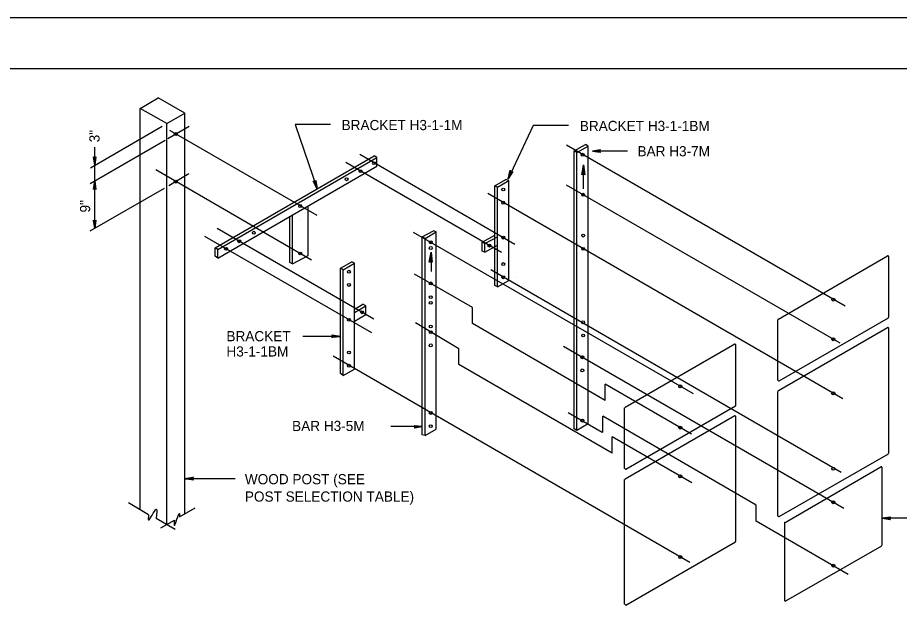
# Model space of a CAD drawing. Extents: x 648590 to 650336, y 294467 to 295061.
# Drawn here: x 649713.9 to 649974.1, y 294884.8 to 295061.4 of the extents above; entities that cross this region are included whole.
import ezdxf

# ---------------------------------------------------------------- set-up
doc = ezdxf.new("R2010")
doc.units = 0
for name, color, linetype in [('1', 7, 'Continuous'), ('2', 7, 'Continuous'), ('3', 7, 'Continuous'), ('PLT-BNDY', 7, 'Continuous')]:
    doc.layers.add(name, color=color, linetype=linetype)

msp = doc.modelspace()

# ---------------------------------------------------------------- linework, layer by layer
at = {"layer": '1'}
msp.add_line((649471.1, 295046.45), (650257.1, 295046.45), dxfattribs=at)
at = {"layer": '2'}
for points in [[(649806.17, 295029.92), (649795.72, 295029.92), (649802.22, 295010.92)], [(649876.38, 295029.67), (649865.97, 295029.67), (649858.6, 295013.92)], [(649885.72, 295021.79), (649885.72, 295021.92), (649883.47, 295022.04), (649885.72, 295021.79), (649885.85, 295021.67), (649883.47, 295022.04), (649885.72, 295022.17), (649885.72, 295022.42), (649883.47, 295022.04), (649885.85, 295022.42), (649885.72, 295022.42)], [(649893.85, 295022.04), (649883.47, 295022.04)], [(649859.85, 295015.92), (649859.6, 295015.92), (649858.6, 295013.92), (649859.85, 295015.92), (649859.97, 295016.04), (649858.6, 295013.92), (649859.47, 295016.04), (649859.35, 295016.17), (649858.6, 295013.92), (649859.22, 295016.42), (649859.35, 295016.17)], [(649801.72, 295013.29), (649801.6, 295013.17), (649802.22, 295010.92), (649801.72, 295013.29), (649801.85, 295013.42), (649802.22, 295010.92), (649801.35, 295013.04), (649801.22, 295013.17), (649802.22, 295010.92), (649801.1, 295013.17), (649801.22, 295013.17)], [(649809.1, 294967.42), (649797.97, 294967.42)], [(649806.72, 294967.79), (649806.85, 294967.54), (649809.1, 294967.42), (649806.72, 294967.79), (649806.6, 294967.92), (649809.1, 294967.42), (649806.85, 294967.29), (649806.85, 294967.17), (649809.1, 294967.42), (649806.6, 294967.04), (649806.85, 294967.17)], [(649833.22, 294940.79), (649824.03, 294940.79)], [(649830.97, 294941.04), (649830.97, 294940.92), (649833.22, 294940.79), (649830.97, 294941.04), (649830.85, 294941.17), (649833.22, 294940.79), (649830.97, 294940.67), (649830.97, 294940.42), (649833.22, 294940.79), (649830.85, 294940.42), (649830.97, 294940.42)], [(649765.6, 294925.17), (649765.47, 294925.29), (649763.22, 294925.42), (649765.6, 294925.17), (649765.72, 294925.04), (649763.22, 294925.42), (649765.47, 294925.54), (649765.6, 294925.79), (649763.22, 294925.42), (649765.72, 294925.92), (649765.6, 294925.79)], [(649778, 294925.42), (649763.22, 294925.42)], [(649971.35, 294913.42), (649971.22, 294913.67), (649968.97, 294913.79), (649971.35, 294913.42), (649971.47, 294913.29), (649968.97, 294913.79), (649971.22, 294913.92), (649971.35, 294914.04), (649968.97, 294913.79), (649971.47, 294914.17), (649971.35, 294914.04)], [(649979.04, 294913.79), (649968.97, 294913.79)]]:
    msp.add_lwpolyline(points, dxfattribs=at)
at = {"layer": '3'}
for p, q in [((649749.97, 295034.67), (649755.35, 295037.79)), ((649763.22, 295033.29), (649755.35, 295037.79)), ((649749.97, 294916.42), (649749.97, 295034.67)), ((649757.85, 295030.17), (649749.97, 295034.67)), ((649757.85, 295030.17), (649763.22, 295033.29)), ((649763.22, 294914.92), (649763.22, 295033.29)), ((649735.35, 295017.17), (649756.47, 295029.42)), ((649757.85, 294911.79), (649757.85, 295030.17)), ((649758.22, 295025.79), (649764.47, 295029.42)), ((649802.22, 295003.04), (649758.72, 295028.17)), ((649760.6, 295027.04), (649760.6, 295027.04)), ((649735.22, 295012.54), (649757.35, 295025.29)), ((649736.6, 295013.34), (649736.6, 295023.19)), ((649958.1, 294976.29), (649875.85, 295023.79)), ((649878.1, 295022.17), (649881.47, 295024.04)), ((649878.85, 295021.67), (649882.22, 295023.54)), ((649882.22, 295023.54), (649881.47, 295024.04)), ((649882.22, 294941.67), (649882.22, 295023.54)), ((649772.1, 294993.54), (649819.1, 295020.67)), ((649860.6, 294994.54), (649814.85, 295021.04)), ((649818.47, 295020.42), (649818.47, 295020.42)), ((649819.85, 295020.17), (649819.1, 295020.67)), ((649878.1, 294940.17), (649878.1, 295022.17)), ((649878.85, 295021.67), (649878.1, 295022.17)), ((649878.85, 294939.67), (649878.85, 295021.67)), ((649772.97, 294993.04), (649819.85, 295020.17)), ((649772.97, 294990.54), (649819.85, 295017.67)), ((649856.6, 294992.17), (649810.72, 295018.67)), ((649819.85, 295017.67), (649819.85, 295020.17)), ((649880.85, 295010.92), (649880.85, 295018.04)), ((649800.6, 294989.92), (649754.6, 295016.54)), ((649758.47, 295011.92), (649764.35, 295015.42)), ((649819.47, 295017.42), (649819.47, 295017.42)), ((649736.6, 294999.29), (649736.6, 295013.29)), ((649760.6, 295013.17), (649760.6, 295013.17)), ((649854.72, 295011.79), (649857.97, 295013.67)), ((649855.47, 295011.42), (649858.85, 295013.42)), ((649858.85, 295013.42), (649857.97, 295013.67)), ((649858.85, 294983.92), (649858.85, 295013.42)), ((649735.22, 294998.54), (649757.22, 295011.17)), ((649854.72, 294982.42), (649854.72, 295011.79)), ((649855.47, 295011.42), (649854.72, 295011.79)), ((649855.47, 294982.04), (649855.47, 295011.42)), ((649956.6, 294965.42), (649875.85, 295012.04)), ((649957.35, 294949.04), (649852.6, 295009.54)), ((649799.6, 294991.29), (649799.6, 295005.92)), ((649789.35, 295002.54), (649789.35, 295002.54)), ((649790.72, 295003.42), (649790.72, 295003.42)), ((649792.1, 295004.17), (649792.1, 295004.17)), ((649794.22, 294989.17), (649794.22, 295002.92)), ((649794.97, 294988.79), (649794.97, 295003.29)), ((649785.1, 295000.17), (649785.1, 295000.17)), ((649786.6, 295001.04), (649786.6, 295001.04)), ((649787.97, 295001.67), (649787.97, 295001.67)), ((649797.22, 295001.54), (649797.22, 295001.54)), ((649818.35, 294968.42), (649769.1, 294996.92)), ((649818.97, 294972.54), (649772.72, 294999.29)), ((649779.72, 294997.04), (649779.72, 294997.04)), ((649781.1, 294997.92), (649781.1, 294997.92)), ((649782.47, 294998.54), (649782.47, 294998.54)), ((649783.85, 294999.42), (649783.85, 294999.42)), ((649913.35, 294950.42), (649830.72, 294998.04)), ((649833.22, 294996.79), (649836.6, 294998.54)), ((649834.1, 294996.29), (649837.35, 294998.29)), ((649837.35, 294998.29), (649836.6, 294998.54)), ((649837.35, 294940.04), (649837.35, 294998.29)), ((649850.97, 294995.17), (649854.72, 294997.29)), ((649775.72, 294994.67), (649775.72, 294994.67)), ((649776.97, 294995.42), (649776.97, 294995.42)), ((649778.35, 294996.17), (649778.35, 294996.17)), ((649779.22, 294995.42), (649779.22, 294995.42)), ((649833.22, 294938.42), (649833.22, 294996.79)), ((649834.1, 294996.29), (649833.22, 294996.79)), ((649834.1, 294938.17), (649834.1, 294996.29)), ((649851.72, 294994.79), (649850.97, 294995.17)), ((649850.97, 294992.54), (649850.97, 294995.17)), ((649851.72, 294994.79), (649855.47, 294996.79)), ((649851.72, 294992.29), (649851.72, 294994.79)), ((649851.72, 294992.29), (649855.47, 294994.29)), ((649772.97, 294993.04), (649772.1, 294993.54)), ((649772.1, 294991.04), (649772.1, 294993.54)), ((649772.97, 294990.54), (649772.97, 294993.04)), ((649772.97, 294993.04), (649772.97, 294993.04)), ((649774.22, 294993.92), (649774.22, 294993.92)), ((649797.22, 294991.92), (649797.22, 294991.92)), ((649835.85, 294992.29), (649835.85, 294986.54)), ((649851.72, 294992.29), (649850.97, 294992.54)), ((649772.97, 294990.54), (649772.1, 294991.04)), ((649794.97, 294988.79), (649794.22, 294989.17)), ((649794.97, 294988.79), (649799.6, 294991.29)), ((649809.1, 294987.54), (649812.47, 294989.42)), ((649809.97, 294987.04), (649813.22, 294989.04)), ((649813.22, 294989.04), (649812.47, 294989.42)), ((649813.22, 294957.79), (649813.22, 294989.04)), ((649938.35, 294972.54), (649970.6, 294991.17)), ((649970.97, 294973.17), (649970.97, 294990.92)), ((649809.1, 294956.42), (649809.1, 294987.54)), ((649809.97, 294987.04), (649809.1, 294987.54)), ((649809.97, 294955.92), (649809.97, 294987.04)), ((649956.85, 294927.29), (649853.47, 294987.04)), ((649848.1, 294975.92), (649830.97, 294985.79)), ((649855.47, 294982.04), (649858.85, 294983.92)), ((649861.1, 294984.79), (649861.1, 294984.79)), ((649855.47, 294982.04), (649854.72, 294982.42)), ((649813.22, 294975.42), (649815.72, 294976.92)), ((649813.22, 294974.42), (649816.6, 294976.42)), ((649816.6, 294976.42), (649815.72, 294976.92)), ((649816.6, 294973.92), (649816.6, 294976.42)), ((649813.22, 294971.92), (649816.6, 294973.92)), ((649815.47, 294974.54), (649815.47, 294974.54)), ((649848.1, 294971.17), (649848.1, 294975.92)), ((649844.1, 294963.79), (649831.22, 294971.42)), ((649887.22, 294948.54), (649848.1, 294971.17)), ((649938.22, 294954.54), (649938.22, 294972.29)), ((649938.6, 294954.29), (649970.85, 294972.92)), ((649815.47, 294970.29), (649815.47, 294970.29)), ((649938.35, 294951.42), (649970.6, 294970.04)), ((649970.97, 294933.04), (649970.97, 294969.79)), ((649844.1, 294959.17), (649844.1, 294963.79)), ((649957.72, 294916.67), (649874.97, 294964.42)), ((649893.1, 294946.54), (649925.47, 294965.17)), ((649925.85, 294947.04), (649925.85, 294964.92)), ((649912.22, 294900.67), (649806.97, 294961.54)), ((649889.35, 294932.92), (649844.1, 294959.17)), ((649809.97, 294955.92), (649809.1, 294956.42)), ((649809.97, 294955.92), (649813.22, 294957.79)), ((649912.72, 294938.54), (649887.22, 294953.29)), ((649887.22, 294948.54), (649887.22, 294953.29)), ((649938.22, 294914.42), (649938.22, 294951.17)), ((649876.35, 294944.92), (649886.35, 294939.17)), ((649892.97, 294928.42), (649892.97, 294946.29)), ((649893.35, 294928.29), (649925.72, 294946.92)), ((649886.6, 294939.04), (649886.6, 294943.92)), ((649931.85, 294917.67), (649886.6, 294943.92)), ((649893.1, 294925.42), (649925.47, 294944.04)), ((649925.85, 294907.04), (649925.85, 294943.79)), ((649834.1, 294938.17), (649837.35, 294940.04)), ((649878.85, 294939.67), (649878.1, 294940.17)), ((649878.85, 294939.79), (649882.22, 294941.67)), ((649834.1, 294938.17), (649833.22, 294938.42)), ((649912.85, 294924.17), (649889.35, 294937.79)), ((649889.35, 294932.92), (649889.35, 294937.79)), ((649938.6, 294914.29), (649970.85, 294932.79)), ((649940.35, 294912.54), (649968.6, 294928.92)), ((649968.97, 294905.92), (649968.97, 294928.79)), ((649892.97, 294888.42), (649892.97, 294925.17)), ((649752.47, 294914.79), (649746.6, 294918.29)), ((649761.6, 294914.17), (649766.22, 294916.79)), ((649931.85, 294912.92), (649931.85, 294917.67)), ((649760.35, 294910.42), (649754.72, 294913.67)), ((649756.1, 294910.92), (649760.1, 294913.17)), ((649958.97, 294897.17), (649931.85, 294912.92)), ((649940.22, 294889.67), (649940.22, 294912.29)), ((649893.35, 294888.17), (649925.72, 294906.79)), ((649940.6, 294889.42), (649968.85, 294905.67))]:
    msp.add_line(p, q, dxfattribs=at)
for points in [[(649736.97, 295020.29), (649736.72, 295020.17), (649736.6, 295017.92), (649736.97, 295020.29), (649736.97, 295020.42), (649736.6, 295017.92), (649736.47, 295020.17), (649736.35, 295020.29), (649736.6, 295017.92), (649736.22, 295020.42), (649736.35, 295020.29)], [(649880.47, 295015.17), (649880.6, 295015.29), (649880.85, 295018.04), (649880.47, 295015.17), (649880.35, 295015.04), (649880.85, 295018.04), (649880.97, 295015.29), (649880.97, 295015.17), (649880.85, 295018.04), (649881.22, 295015.04), (649880.97, 295015.17)], [(649736.35, 295010.92), (649736.47, 295010.92), (649736.6, 295013.29), (649736.35, 295010.92), (649736.22, 295010.79), (649736.6, 295013.29), (649736.72, 295010.92), (649736.97, 295010.92), (649736.6, 295013.29), (649736.97, 295010.79), (649736.97, 295010.92)], [(649736.97, 295001.54), (649736.72, 295001.54), (649736.6, 294999.29), (649736.97, 295001.54), (649736.97, 295001.67), (649736.6, 294999.29), (649736.47, 295001.54), (649736.35, 295001.54), (649736.6, 294999.29), (649736.22, 295001.67), (649736.35, 295001.54)], [(649835.47, 294989.42), (649835.72, 294989.42), (649835.85, 294992.29), (649835.47, 294989.42), (649835.35, 294989.29), (649835.85, 294992.29), (649835.97, 294989.42), (649836.1, 294989.42), (649835.85, 294992.29), (649836.22, 294989.29), (649836.1, 294989.42)]]:
    msp.add_lwpolyline(points, dxfattribs=at)
for centre in [(649760.5, 295027.1), (649880.59, 295021), (649819.05, 295018.53), (649815.04, 295016.15), (649760.5, 295013.09), (649810.94, 295013.78), (649857.17, 295010.75), (649857.17, 295006.86), (649880.74, 295009.21), (649797.25, 295005.88), (649783.56, 294997.98), (649857.17, 294996.56), (649880.74, 294997.14), (649779.25, 294995.49), (649835.77, 294995.17), (649853.07, 294994.19), (649775.35, 294993.24), (649797.25, 294991.87), (649835.77, 294993.49), (649880.74, 294993.25), (649857.17, 294988.76), (649811.63, 294986.48), (649857.17, 294984.87), (649811.63, 294982.59), (649835.77, 294983.04), (649835.77, 294978.98), (649954.57, 294978.28), (649835.77, 294977.3), (649815.53, 294974.54), (649811.63, 294972.29), (649880.74, 294971.56), (649835.77, 294970.34), (649835.77, 294968.66), (649880.74, 294967.67), (649954.57, 294966.57), (649811.63, 294962.66), (649835.76, 294964.77), (649880.51, 294961.26), (649811.63, 294958.77), (649880.5, 294957.37), (649909.42, 294952.65), (649954.57, 294950.61), (649835.77, 294944.84), (649880.51, 294942.58), (649835.76, 294940.94), (649909.42, 294940.51), (649954.57, 294928.37), (649909.42, 294926.13), (649954.57, 294918.49), (649909.42, 294902.31), (649954.57, 294899.8)]:
    msp.add_circle(centre, 0.428, dxfattribs=at)
for centre, start, end in [((649970.67, 294990.95), 0, 119.9917), ((649938.47, 294972.36), 119.9995, 180), ((649970.67, 294973.1), 299.9933, 0), ((649970.67, 294969.83), 0, 119.9855), ((649925.52, 294964.89), 0, 119.9917), ((649938.47, 294954.51), 180, 299.9946), ((649938.47, 294951.24), 120.0061, 180), ((649893.32, 294946.3), 119.9995, 180), ((649925.52, 294947.04), 299.9933, 0), ((649925.52, 294943.77), 0, 119.999), ((649970.67, 294933.1), 299.9962, 0), ((649893.32, 294928.45), 180, 299.9946), ((649968.72, 294928.7), 0, 119.9857), ((649893.32, 294925.18), 120.001, 180), ((649938.47, 294914.51), 180, 299.9902), ((649940.42, 294912.36), 119.9982, 180), ((649925.52, 294907.03), 299.9789, 0), ((649968.72, 294905.92), 299.9948, 0), ((649893.32, 294888.45), 180, 299.9917), ((649940.42, 294889.58), 180, 299.9954)]:
    msp.add_arc(centre, 0.249, start, end, dxfattribs=at)
for points in [[(649752.47, 294914.79), (649752.47, 294913.29), (649754.72, 294916.42), (649754.72, 294913.67)], [(649760.1, 294913.17), (649760.1, 294911.67), (649761.6, 294915.17), (649761.6, 294914.17)]]:
    msp.add_spline(points, degree=3, dxfattribs=at)
at = {"layer": 'PLT-BNDY'}
msp.add_lwpolyline([(649431.1, 295061.45), (650272.1, 295061.45), (650272.1, 294467.45), (649431.1, 294467.45)], close=True, dxfattribs=at)

# ---------------------------------------------------------------- texts
at = {"layer": '3'}
for s, p in [('BRACKET H3-1-1M', (649809.46, 295028.26)), ('BRACKET H3-1-1BM', (649879.76, 295028)), ('BAR H3-7M', (649896.78, 295020.54)), ('BRACKET', (649775.47, 294965.98)), ('H3-1-1BM', (649775.47, 294961.48)), ('BAR H3-5M', (649794.85, 294939.5)), ('WOOD POST (SEE', (649780.91, 294923.79)), ('POST SELECTION TABLE)', (649780.91, 294918.67))]:
    msp.add_text(s, height=3, dxfattribs=at).set_placement(p)
for s, p in [('3"', (649738.03, 295024.66)), ('9"', (649735.25, 295003.97))]:
    msp.add_text(s, height=3, rotation=90, dxfattribs=at).set_placement(p)

doc.saveas('drawing.dxf')
